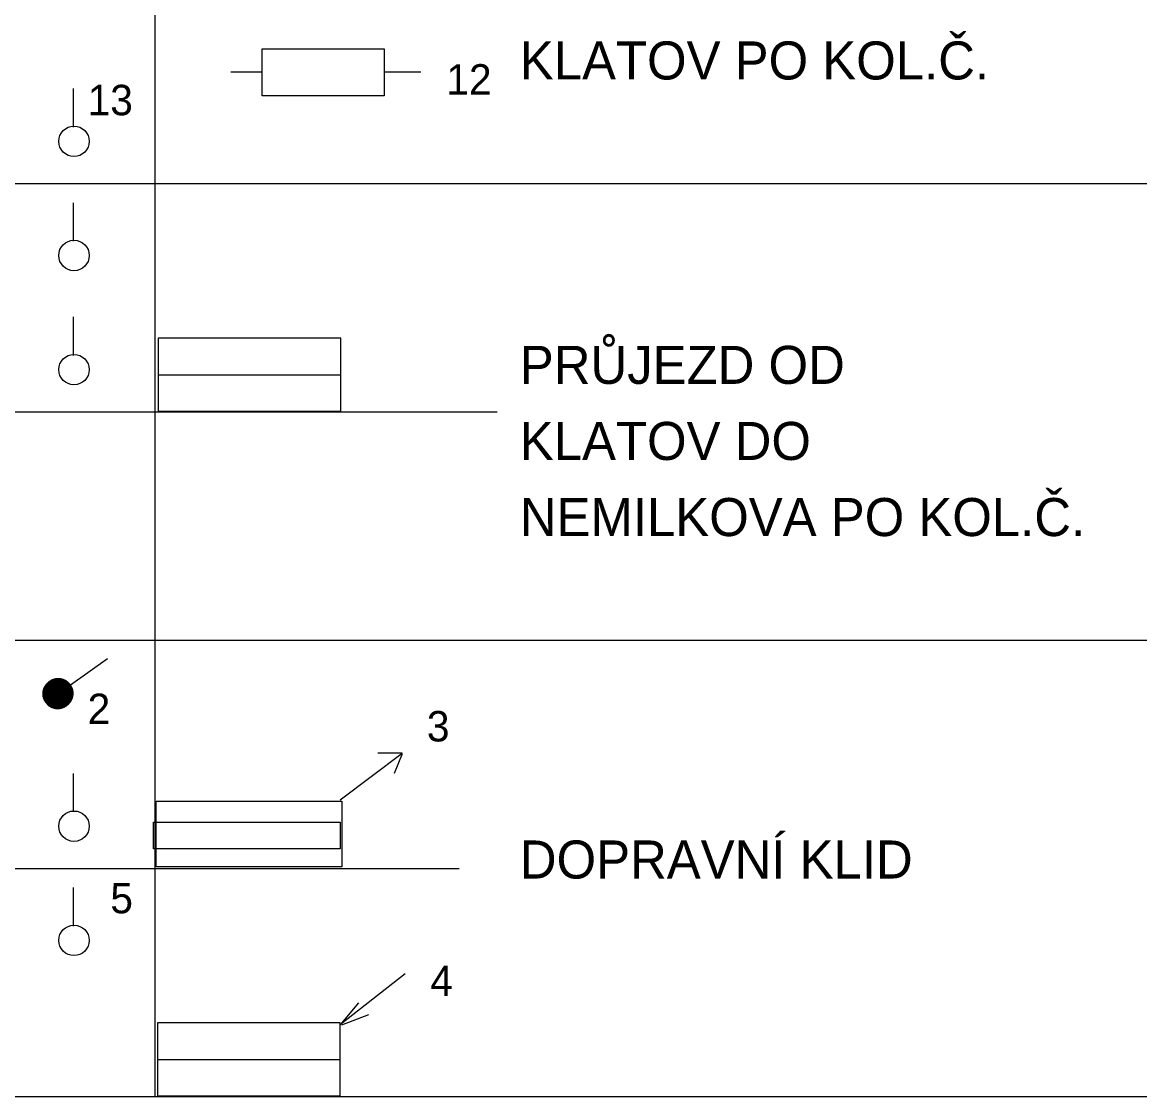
# Model space of a CAD drawing. Extents: x -28 to 822, y 61 to 665.
# Drawn here: x 264.4 to 337.9, y 111.7 to 182.3 of the extents above; entities that cross this region are included whole.
import ezdxf

# ---------------------------------------------------------------- set-up
doc = ezdxf.new("R2010")
doc.units = 0
doc.layers.add('KOLEJIŠTĚ', color=7, linetype='Continuous')

# ---------------------------------------------------------------- blocks, each defined once
blk = doc.blocks.new('_X10')
for p, q in [((370.452, 480.16), (371.464, 481.172)), ((370.452, 480.177), (371.447, 481.172)), ((370.452, 480.195), (371.429, 481.172)), ((370.453, 480.142), (371.482, 481.172)), ((370.453, 480.125), (371.499, 481.171)), ((370.453, 480.214), (371.411, 481.171)), ((370.454, 480.109), (371.515, 481.17)), ((370.454, 480.232), (371.392, 481.17)), ((370.455, 480.092), (371.532, 481.169)), ((370.455, 480.251), (371.373, 481.169)), ((370.457, 480.076), (371.548, 481.167)), ((370.457, 480.271), (371.353, 481.167)), ((370.458, 480.06), (371.564, 481.166)), ((370.459, 480.291), (371.334, 481.165)), ((370.46, 480.044), (371.58, 481.164)), ((370.462, 480.029), (371.596, 481.162)), ((370.462, 480.311), (371.313, 481.162)), ((370.465, 480.013), (371.611, 481.159)), ((370.465, 480.332), (371.293, 481.159)), ((370.467, 479.998), (371.626, 481.157)), ((370.469, 480.353), (371.271, 481.156)), ((370.47, 479.983), (371.641, 481.154)), ((370.473, 479.969), (371.656, 481.151)), ((370.473, 480.375), (371.249, 481.151)), ((370.476, 479.954), (371.67, 481.148)), ((370.478, 480.398), (371.227, 481.146)), ((370.479, 479.94), (371.685, 481.145)), ((370.483, 479.925), (371.699, 481.141)), ((370.484, 480.421), (371.203, 481.141)), ((370.487, 479.911), (371.713, 481.137)), ((370.49, 480.445), (371.179, 481.134)), ((370.491, 479.898), (371.727, 481.134)), ((370.495, 479.884), (371.74, 481.13)), ((370.498, 480.47), (371.154, 481.126)), ((370.499, 479.87), (371.754, 481.125)), ((370.503, 479.857), (371.767, 481.121)), ((370.506, 480.497), (371.127, 481.118)), ((370.507, 479.844), (371.78, 481.117)), ((370.512, 479.831), (371.793, 481.112)), ((370.516, 480.524), (371.1, 481.108)), ((370.517, 479.818), (371.806, 481.107)), ((370.522, 479.805), (371.819, 481.102)), ((370.527, 479.793), (371.832, 481.097)), ((370.528, 480.554), (371.071, 481.096)), ((370.532, 479.78), (371.844, 481.092)), ((370.537, 479.768), (371.856, 481.087)), ((370.541, 480.585), (371.039, 481.083)), ((370.543, 479.756), (371.869, 481.081)), ((370.549, 479.744), (371.881, 481.076)), ((370.554, 479.732), (371.893, 481.07)), ((370.557, 480.618), (371.006, 481.067)), ((370.56, 479.72), (371.904, 481.064)), ((370.566, 479.708), (371.916, 481.058)), ((370.572, 479.697), (371.928, 481.052)), ((370.577, 480.656), (370.968, 481.047)), ((370.579, 479.685), (371.939, 481.046)), ((370.585, 479.674), (371.95, 481.039)), ((370.592, 479.663), (371.961, 481.033)), ((370.598, 479.652), (371.972, 481.026)), ((370.602, 480.698), (370.926, 481.022)), ((370.605, 479.641), (371.983, 481.019)), ((370.612, 479.63), (371.994, 481.012)), ((370.619, 479.619), (372.005, 481.005)), ((370.626, 479.609), (372.015, 480.998)), ((370.633, 479.598), (372.026, 480.991)), ((370.637, 480.751), (370.873, 480.988)), ((370.64, 479.588), (372.036, 480.984)), ((370.648, 479.578), (372.046, 480.976)), ((370.655, 479.568), (372.057, 480.969)), ((370.663, 479.558), (372.067, 480.961)), ((370.671, 479.548), (372.076, 480.953)), ((370.679, 479.538), (372.086, 480.945)), ((370.687, 479.528), (372.096, 480.937)), ((370.695, 479.519), (372.105, 480.929)), ((370.703, 479.509), (372.115, 480.921)), ((370.706, 480.838), (370.786, 480.918)), ((370.712, 479.5), (372.124, 480.913)), ((370.72, 479.491), (372.133, 480.904)), ((370.729, 479.482), (372.142, 480.896)), ((370.737, 479.473), (372.151, 480.887)), ((370.746, 479.464), (372.16, 480.878)), ((370.755, 479.455), (372.169, 480.869)), ((370.764, 479.446), (372.178, 480.86)), ((370.773, 479.438), (372.186, 480.851)), ((370.782, 479.429), (372.195, 480.842)), ((370.792, 479.421), (372.203, 480.832)), ((370.801, 479.413), (372.211, 480.823)), ((370.811, 479.405), (372.219, 480.813)), ((370.821, 479.397), (372.227, 480.804)), ((370.83, 479.389), (372.235, 480.794)), ((370.84, 479.381), (372.243, 480.784)), ((370.85, 479.373), (372.251, 480.774)), ((370.86, 479.366), (372.258, 480.764)), ((370.871, 479.358), (372.266, 480.754)), ((370.881, 479.351), (372.273, 480.743)), ((370.891, 479.344), (372.28, 480.733)), ((370.902, 479.337), (372.287, 480.722)), ((370.913, 479.33), (372.294, 480.711)), ((370.924, 479.323), (372.301, 480.701)), ((370.935, 479.316), (372.308, 480.69)), ((370.946, 479.31), (372.314, 480.678)), ((370.957, 479.303), (372.321, 480.667)), ((370.968, 479.297), (372.327, 480.656)), ((370.98, 479.291), (372.333, 480.645)), ((370.991, 479.285), (372.34, 480.633)), ((371.003, 479.279), (372.346, 480.621)), ((371.015, 479.273), (372.351, 480.609)), ((371.027, 479.267), (372.357, 480.597)), ((371.039, 479.261), (372.363, 480.585)), ((371.051, 479.256), (372.368, 480.573)), ((371.063, 479.251), (372.373, 480.561)), ((371.076, 479.246), (372.379, 480.548)), ((371.089, 479.24), (372.384, 480.536)), ((371.101, 479.236), (372.389, 480.523)), ((371.114, 479.231), (372.393, 480.51)), ((371.127, 479.226), (372.398, 480.497)), ((371.141, 479.222), (372.402, 480.484)), ((371.154, 479.218), (372.407, 480.47)), ((371.167, 479.213), (372.411, 480.457)), ((371.181, 479.209), (372.415, 480.443)), ((371.195, 479.206), (372.419, 480.429)), ((371.209, 479.202), (372.422, 480.415)), ((371.223, 479.199), (372.426, 480.401)), ((371.238, 479.195), (372.429, 480.386)), ((371.252, 479.192), (372.432, 480.372)), ((371.267, 479.189), (372.435, 480.357)), ((371.282, 479.187), (372.438, 480.342)), ((371.297, 479.184), (372.44, 480.327)), ((371.313, 479.182), (372.442, 480.311)), ((371.328, 479.18), (372.444, 480.296)), ((371.344, 479.178), (372.446, 480.28)), ((371.36, 479.176), (372.448, 480.264)), ((371.376, 479.175), (372.449, 480.248)), ((371.393, 479.174), (372.45, 480.231)), ((371.41, 479.173), (372.451, 480.214)), ((371.427, 479.172), (372.452, 480.197)), ((371.444, 479.172), (372.452, 480.18)), ((371.462, 479.172), (372.452, 480.162)), ((371.48, 479.172), (372.452, 480.144)), ((371.498, 479.173), (372.451, 480.126)), ((371.517, 479.174), (372.45, 480.107)), ((371.536, 479.176), (372.449, 480.088)), ((371.556, 479.177), (372.447, 480.068)), ((371.576, 479.18), (372.444, 480.048)), ((371.596, 479.182), (372.442, 480.028)), ((371.617, 479.186), (372.438, 480.007)), ((371.639, 479.19), (372.435, 479.985)), ((371.661, 479.194), (372.43, 479.963)), ((371.684, 479.199), (372.425, 479.941)), ((371.707, 479.205), (372.419, 479.917)), ((371.732, 479.212), (372.412, 479.892)), ((371.757, 479.22), (372.404, 479.867)), ((371.784, 479.229), (372.395, 479.84)), ((371.812, 479.239), (372.385, 479.812)), ((371.841, 479.251), (372.373, 479.783)), ((371.873, 479.265), (372.359, 479.751)), ((371.908, 479.282), (372.342, 479.716)), ((371.946, 479.303), (372.322, 479.678)), ((371.991, 479.329), (372.295, 479.634)), ((372.047, 479.369), (372.256, 479.577))]:
    blk.add_line(p, q)
blk = doc.blocks.new('ZT18')
for p, q in [((10, 6), (0, 6)), ((0, 6), (0, 2)), ((10, 2), (10, 6)), ((0, 2), (10, 2))]:
    blk.add_line(p, q)
blk.add_lwpolyline([(0, 4), (0, 4), (10, 4)])

msp = doc.modelspace()

# ---------------------------------------------------------------- linework, layer by layer
for p, q in [((273.116, 381.738), (273.116, 111.738)), ((273.116, 381.738), (273.116, 111.738)), ((280.169, 179.046), (278.116, 179.046)), ((290.616, 179.046), (288.193, 179.046)), ((267.778, 175.441), (267.778, 177.974)), ((5.068, 171.738), (540.616, 171.738)), ((267.778, 167.941), (267.778, 170.474)), ((267.778, 160.441), (267.778, 162.974)), ((5.068, 156.738), (295.616, 156.738)), ((5.068, 141.738), (540.616, 141.738)), ((267.57, 138.796), (270.019, 140.529)), ((285.295, 131.236), (289.379, 134.297)), ((289.379, 134.297), (287.775, 134.297)), ((289.386, 134.255), (288.847, 132.962)), ((267.778, 130.441), (267.778, 132.974)), ((5.068, 126.738), (293.116, 126.738)), ((267.778, 122.941), (267.778, 125.474)), ((285.316, 116.51), (289.575, 119.819)), ((285.413, 116.571), (286.522, 117.9)), ((285.413, 116.461), (287.187, 117.125)), ((5.068, 111.738), (540.616, 111.738))]:
    msp.add_line(p, q)
for points in [[(288.193, 177.492), (280.169, 177.492), (280.169, 180.586), (288.193, 180.586)], [(285.408, 126.84), (273.218, 126.84), (273.218, 131.154), (285.408, 131.154)], [(285.295, 128.029), (273.04, 128.029), (273.04, 129.779), (285.295, 129.779)]]:
    msp.add_lwpolyline(points, close=True)
for centre in [(267.81, 174.505), (267.81, 167.005), (267.81, 159.505), (267.81, 129.505), (267.81, 122.005)]:
    msp.add_circle(centre, 1)

# ---------------------------------------------------------------- block references
at = {"rotation": -92.29148628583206}
msp.add_blockref('_X10', (-198.183, 528.572), dxfattribs=at)
at = {"layer": 'KOLEJIŠTĚ', "xscale": 1.2000000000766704, "yscale": 1.2000000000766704}
for p in [(273.343, 154.37), (273.304, 109.383)]:
    msp.add_blockref('ZT18', p, dxfattribs=at)

# ---------------------------------------------------------------- texts
for s, height, p in [('KLATOV PO KOL.Č.', 2.5, (297.113, 178.569)), ('12', 2, (292.281, 177.574)), ('13', 2, (268.705, 176.219)), ('PRŮJEZD OD', 2.5, (297.113, 158.569)), ('KLATOV DO', 2.5, (297.113, 153.569)), ('NEMILKOVA PO KOL.Č.', 2.5, (297.113, 148.569)), ('2', 2, (268.705, 136.219)), ('3', 2, (291.003, 135.076)), ('DOPRAVNÍ KLID', 2.5, (297.113, 126.069)), ('5', 2, (270.198, 123.784)), ('4', 2, (291.224, 118.352))]:
    msp.add_text(s, height=height).set_placement(p)

doc.saveas('drawing.dxf')
